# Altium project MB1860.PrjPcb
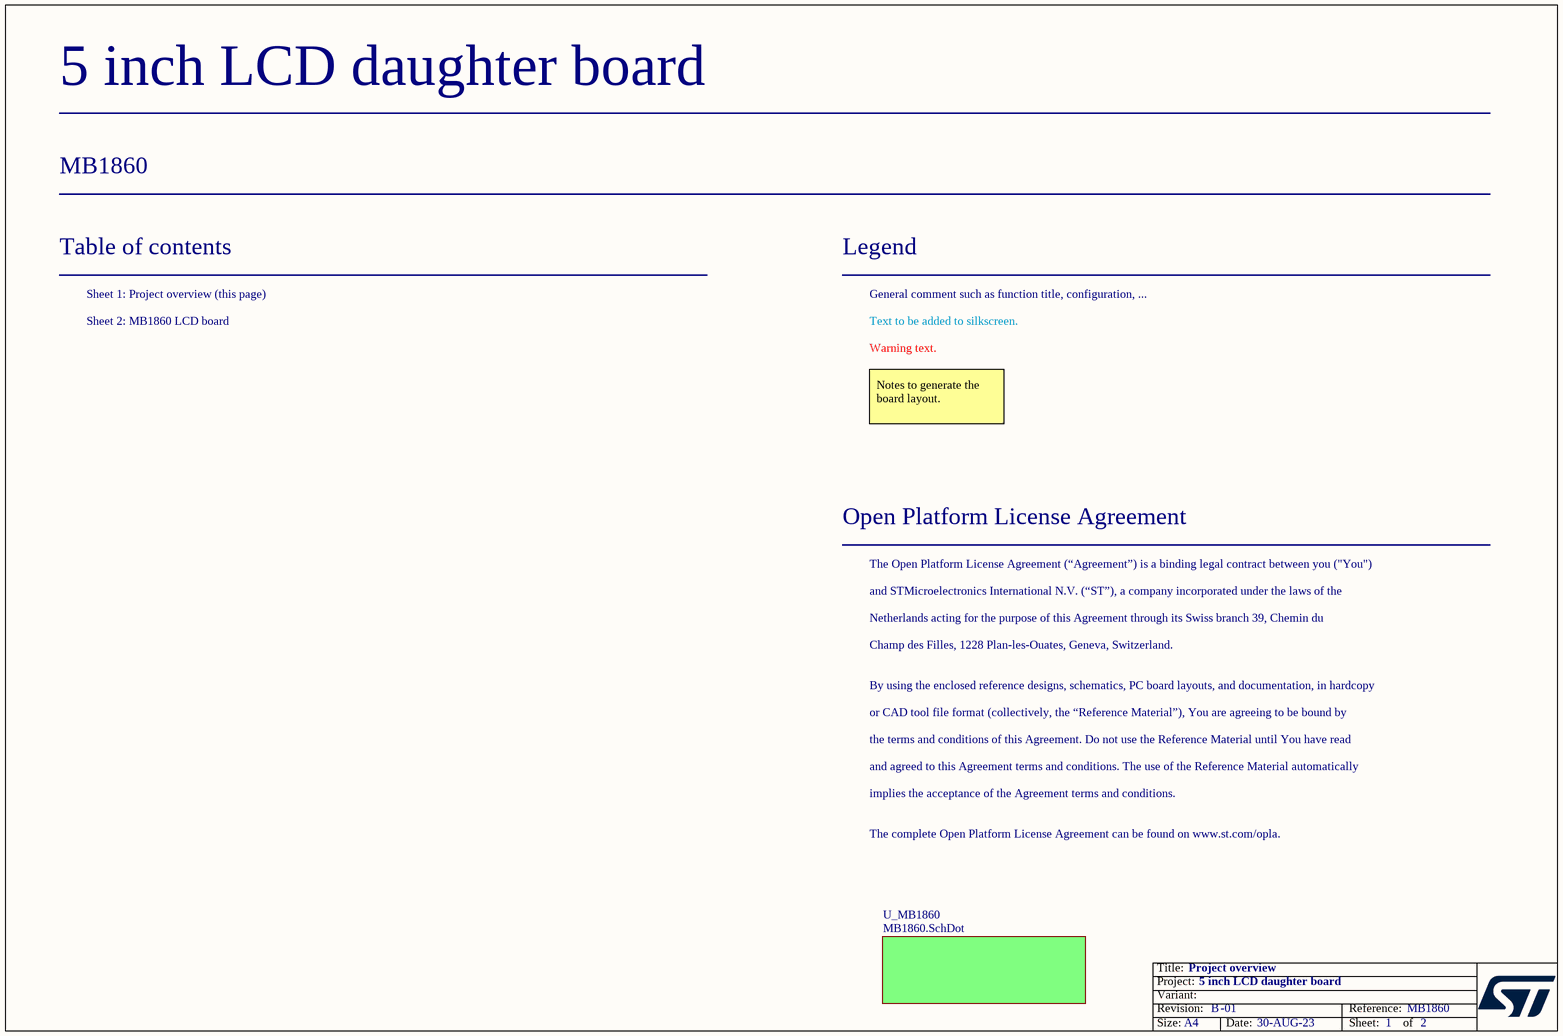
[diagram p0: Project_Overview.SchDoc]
Board_Assembly_Revision: 01; Board_Document_Date: 30-AUG-23; Board_Name: 5 inch LCD daughter board; Board_PCB_Revision: B; Board_Reference: MB1860
2 sheets, 42 parts. Net scope: global (net labels, ports and power ports of the same name join across sheets).
Board file: MB1860.PcbDoc
Sheets:
  Project_Overview.SchDoc
  MB1860.SchDoc

## Sheet Project_Overview.SchDoc: Project overview
size A4; Date: Not used; ApprovedBy: Not used; CheckedBy: Not used; Author: Not used; CompanyName: STMicroelectronics; DrawnBy: Not used; Engineer: Not used; Organization: Not used; Address1: Not used; Address2: Not used; Address3: Not used; Address4: Not used; DocumentNumber: Not used; Revision: Not used; SheetNumber: 1; SheetTotal: 2

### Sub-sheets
U_MB1860 = MB1860.SchDot (file not in this document): no entries

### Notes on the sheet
- Table of contents
- Sheet 1: Project overview (this page)
- Legend
- General comment such as function title, configuration, ...
- Sheet 2: MB1860 LCD board
- Text to be added to silkscreen.
- Warning text.
- Notes to generate the board layout.
- Open Platform License Agreement
- The Open Platform License Agreement (“Agreement”) is a binding legal contract between you ("You")
- and STMicroelectronics International N.V. (“ST”), a company incorporated under the laws of the
- Netherlands acting for the purpose of this Agreement through its Swiss branch 39, Chemin du
- Champ des Filles, 1228 Plan-les-Ouates, Geneva, Switzerland.
- By using the enclosed reference designs, schematics, PC board layouts, and documentation, in hardcopy
- or CAD tool file format (collectively, the “Reference Material”), You are agreeing to be bound by
- the terms and conditions of this Agreement. Do not use the Reference Material until You have read
- and agreed to this Agreement terms and conditions. The use of the Reference Material automatically
- implies the acceptance of the Agreement terms and conditions.
- The complete Open Platform License Agreement can be found on www.st.com/opla.

## Sheet MB1860.SchDoc: MB1860
size A4; Date: Not used; ApprovedBy: Not used; CheckedBy: Not used; Author: Not used; CompanyName: STMicroelectronics; DrawnBy: Not used; Engineer: Not used; Organization: Not used; Address1: Not used; Address2: Not used; Address3: Not used; Address4: Not used; DocumentNumber: Not used; Revision: Not used; SheetNumber: 2; SheetTotal: 2
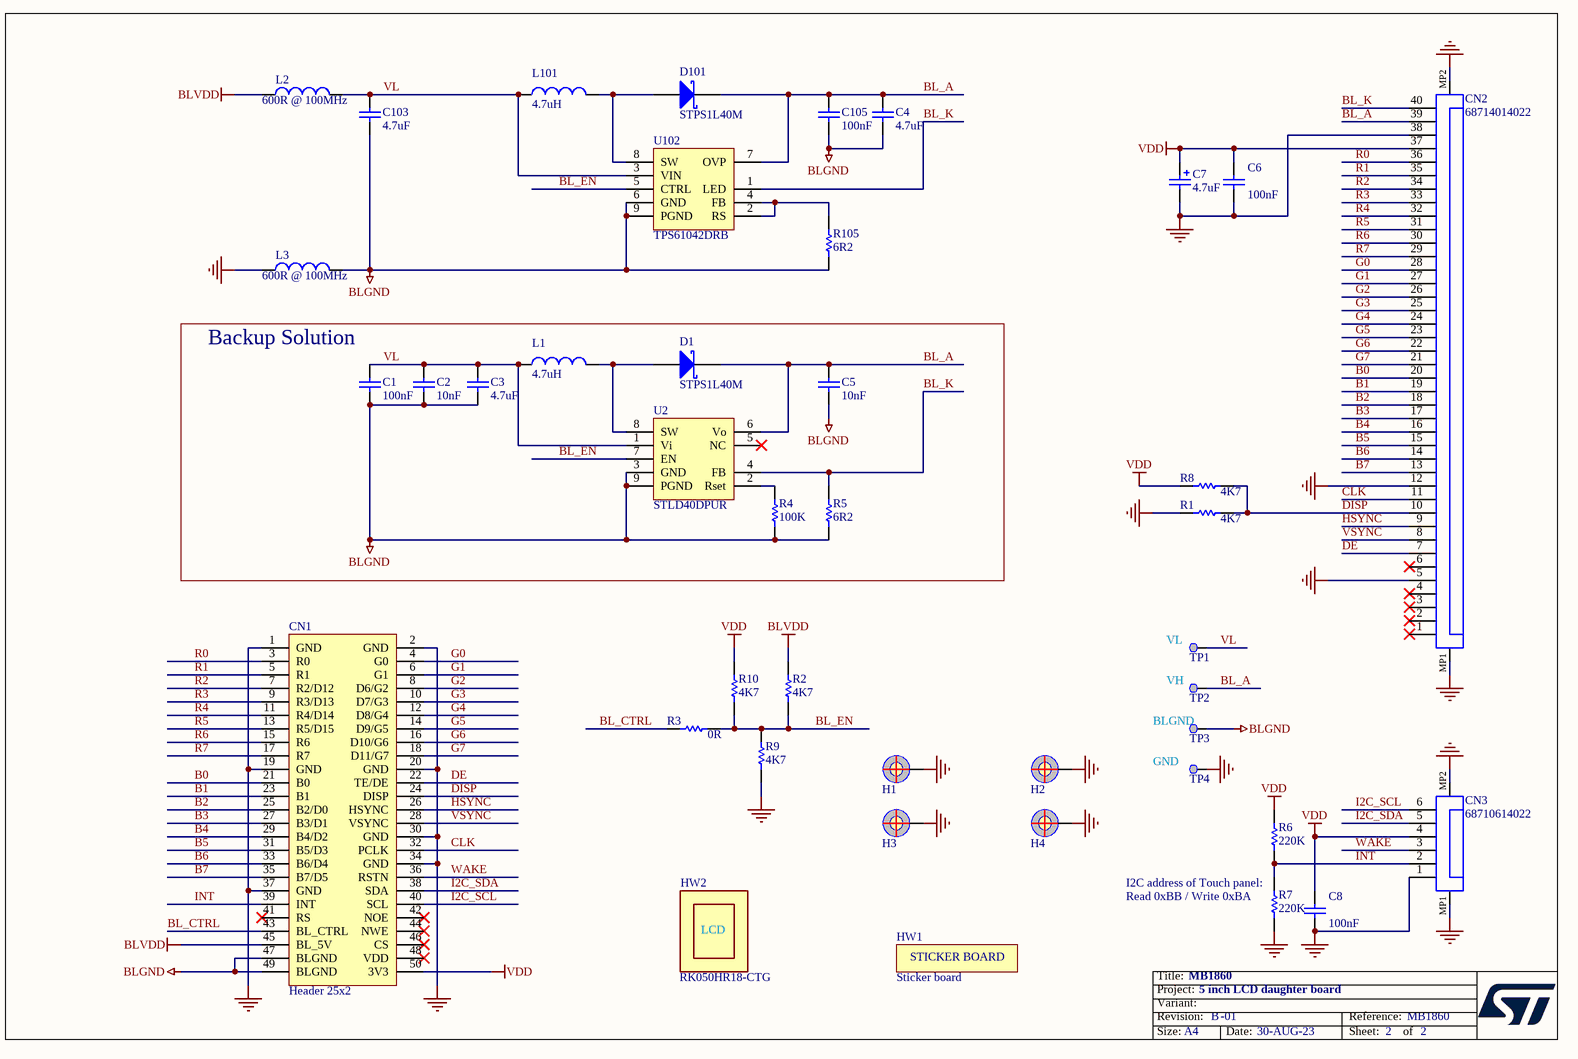
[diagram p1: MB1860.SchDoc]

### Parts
C1  value 100nF  [C0603]  (hidden comment: Capacitor)
C2  value 10nF  [C0603]  (hidden comment: Capacitor)
C3  value 4.7uF  [C1206_H1P25]  (hidden comment: Capacitor)
C4  value 4.7uF  [C1206_H1P25]  (hidden comment: Capacitor)
C5  value 10nF  [C0603]  (hidden comment: Capacitor)
C6  value 100nF  [C0603]  (hidden comment: Capacitor)
C7  value 4.7uF  [CPOL_TAJ-A_1206_H180]  (hidden comment: Cap_POL_TANA)
C8  value 100nF  [C0603]  (hidden comment: Capacitor)
C103  value 4.7uF  [C1206_H1P25]  (hidden comment: Capacitor)
C105  value 100nF  [C0603]  (hidden comment: Capacitor)
CN1  value Header 25x2  [CON_SAMTEC_FTSH-125-01-F-DV-K]  (hidden comment: Header 25x2 LCD MODULE)
CN2  68714014022  [CON_WE_68714014022]
CN3  68710614022  [CON_WE_68710614022]
D1  STPS1L40M  [DIO_DO216-AA]
D101  STPS1L40M  [DIO_DO216-AA]
H1  POSITION HOLE  [PTH_450_900]  (value not drawn)  (no BOM)
H2  POSITION HOLE  [PTH_450_900]  (value not drawn)  (no BOM)
H3  POSITION HOLE  [PTH_450_900]  (value not drawn)  (no BOM)
H4  POSITION HOLE  [PTH_450_900]  (value not drawn)  (no BOM)
HW1  value Sticker board  [STICKER_BOARD_25X9]  (hidden comment: STICKER_BOARD)  (no BOM)
HW2  value RK050HR18-CTG  [LCD_DRAWING_ROCKTEK_RK050HR18-CTG]  (hidden comment: LCD_MODULE)
L1  value 4.7uH  [L1210_LQH]  (hidden comment: Inductor)
L2  value 600R @ 100MHz  [L0603]  (hidden comment: BEAD)
L3  value 600R @ 100MHz  [L0603]  (hidden comment: BEAD)
L101  value 4.7uH  [L1210_LQH]  (hidden comment: Inductor)
R1  value 4K7  [R0603]  (hidden comment: Resistor)
R2  value 4K7  [R0603]  (hidden comment: Resistor)
R3  value 0R  [R0603]  (hidden comment: Resistor)
R4  value 100K  [R0603]  (hidden comment: Resistor)
R5  value 6R2  [R0805_H0P5]  (hidden comment: Resistor)
R6  value 220K  [R0603]  (hidden comment: Resistor)
R7  value 220K  [R0603]  (hidden comment: Resistor)
R8  value 4K7  [R0603]  (hidden comment: Resistor)
R9  value 4K7  [R0603]  (hidden comment: Resistor)
R10  value 4K7  [R0603]  (hidden comment: Resistor)
R105  value 6R2  [R0805_H0P5]  (hidden comment: Resistor)
TP1  Test Point  [TP_SMD_2MM]  (value not drawn)  (no BOM)
TP2  Test Point  [TP_SMD_2MM]  (value not drawn)  (no BOM)
TP3  Test Point  [TP_SMD_2MM]  (value not drawn)  (no BOM)
TP4  Test Point  [TP_SMD_2MM]  (value not drawn)  (no BOM)
U2  STLD40DPUR  [ICC_QFN8-EPAD_3X3_P065]
U102  TPS61042DRB  [ICC_QFN8-EPAD_3X3_P065]

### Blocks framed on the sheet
Backup Solution: C1-C3 C5 D1 L1 R4 R5 U2

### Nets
BLGND: C1.1 C2.1 C3.1 C4.1 C5.1 C103.1 C105.1 CN1.47(BLGND) CN1.49(BLGND) L3.2 R4.1 R5.1 R105.1 TP3.1 U2.3(GND) U2.9(PGND) U102.6(GND) U102.9(PGND)
BLVDD: CN1.45(BL_5V) L2.1 R2.1
GND: C6.1 C7.2 C8.1 CN1.1(GND) CN1.2(GND) CN1.19(GND) CN1.20(GND) CN1.30(GND) CN1.34(GND) CN1.37(GND) CN2.5 CN2.12 CN2.38 CN2.MP1 CN2.MP2 CN3.1 CN3.MP1 CN3.MP2 H1.1 H2.1 H3.1 H4.1 L3.1 R1.1 R7.1 R9.2 TP4.1
VDD: C6.2 C7.1 C8.2 CN1.50(3V3) CN2.37 CN3.4 R6.2 R8.1 R10.1
B0: CN1.21(B0) CN2.20
B1: CN1.23(B1) CN2.19
B2: CN1.25(B2/D0) CN2.18
B3: CN1.27(B3/D1) CN2.17
B4: CN1.29(B4/D2) CN2.16
B5: CN1.31(B5/D3) CN2.15
B6: CN1.33(B6/D4) CN2.14
B7: CN1.35(B7/D5) CN2.13
BL_A: C4.2 C5.2 C105.2 CN2.39 D1.2(K) D101.2(K) TP2.1 U2.6(Vo) U102.7(OVP)
BL_CTRL: CN1.43(BL_CTRL) R3.1
BL_EN: R2.2 R3.2 R9.1 R10.2 U2.7(EN) U102.5(CTRL)
BL_K: CN2.40 R5.2 U2.4(FB) U102.1(LED)
CLK: CN1.32(PCLK) CN2.11
DE: CN1.22(TE/DE) CN2.7
DISP: CN1.24(DISP) CN2.10 R1.2 R8.2
G0: CN1.4(G0) CN2.28
G1: CN1.6(G1) CN2.27
G2: CN1.8(D6/G2) CN2.26
G3: CN1.10(D7/G3) CN2.25
G4: CN1.12(D8/G4) CN2.24
G5: CN1.14(D9/G5) CN2.23
G6: CN1.16(D10/G6) CN2.22
G7: CN1.18(D11/G7) CN2.21
HSYNC: CN1.26(HSYNC) CN2.9
I2C_SCL: CN1.40(SCL) CN3.6
I2C_SDA: CN1.38(SDA) CN3.5
INT: CN1.39(INT) CN3.2 R6.1 R7.2
R0: CN1.3(R0) CN2.36
R1: CN1.5(R1) CN2.35
R2: CN1.7(R2/D12) CN2.34
R3: CN1.9(R3/D13) CN2.33
R4: CN1.11(R4/D14) CN2.32
R5: CN1.13(R5/D15) CN2.31
R6: CN1.15(R6) CN2.30
R7: CN1.17(R7) CN2.29
VL: C1.2 C2.2 C3.2 C103.2 L1.1 L2.2 L101.1 TP1.1 U2.1(Vi) U102.3(VIN)
VSYNC: CN1.28(VSYNC) CN2.8
WAKE: CN1.36(RSTN) CN3.3
NetD1_1: D1.1(A) L1.2 U2.8(SW)
NetD101_1: D101.1(A) L101.2 U102.8(SW)
NetR4_2: R4.2 U2.2(Rset)
NetR105_2: R105.2 U102.2(RS) U102.4(FB)

Not connected (* = marked no-connect by the designer): CN1 41(RS)* 42(NOE)* 44(NWE)* 46(CS)* 48(VDD)*; CN2 1* 2* 3* 4* 6*; U2 5(NC)*

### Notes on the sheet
- (near TP1) VL
- (near TP3) BLGND
- (near TP2) VH
- GND
- (near R7) I2C address of Touch panel:
- (near R7) Read 0xBB / Write 0xBA
- Title:
- Project:
- Size:
- Revision:
- Variant:
- A4
- -
- Date:
- Reference:
- Sheet:
- of

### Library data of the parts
C1 C6 C8 = MCD-00211: Capacitor, MLCC, 100nF, 16V, X7R, +/-10%, 0603, T=0.8mm; Part_Preference: Recommended; Manufacturer: YAGEO; Manufacturer_Part_Number: CC0603KRX7R7BB104; Order_Code_RS: 669-8763; Component_Country_Of_Origin: China; ShowFields: YES; ID: 2659
C2 C5 = MCD-00017: Capacitor, MLCC, 10nF, 50V, X7R, +/-10%, 0603, T=0.8mm; Part_Preference: Recommended; Manufacturer: YAGEO; Manufacturer_Part_Number: CC0603KRX7R9BB103; Order_Code_RS: 616-9537; Component_Country_Of_Origin: China; ShowFields: YES; ID: 2500
C3 C4 C103 = MCD-00013: Capacitor, MLCC, 4.7uF, 50V, X7R, +/-10%, 1206, T=1.27mm; Part_Preference: Recommended; Manufacturer: AVX; Manufacturer_Part_Number: 12065C475KAT2A; Order_Code_RS: 178-0947; Component_Country_Of_Origin: China, Penang; ShowFields: YES; ID: 2466
C7 = MCD-00007: Capacitor, Tantalum, 4.7uF, 16V, 4R, +/-10%, Type_A (3216 metric), T=1.6mm; Part_Preference: Recommended; Manufacturer: AVX; Manufacturer_Part_Number: TAJA475K016R; Order_Code_RS: 464-9132; Component_Country_Of_Origin: El Salvador; ShowFields: YES; ID: 2473
C105 = MCD-01099: Capacitor, MLCC, 100nF, 50V, X7R, +/-10%, 0603, T=0.8mm; BMS_Part_Number: 9142278; Part_Preference: Recommended; Manufacturer: YAGEO; Manufacturer_Part_Number: CC0603KRX7R9BB104; Order_Code_RS: 669-8767; Component_Country_Of_Origin: China; ShowFields: YES; ID: 3397
CN1 = MCD-01187: Header, 25x2, 1.27mm, VR, SMD, T=3.05mm; Part_Type: Connector; Part_Preference: Recommended; Manufacturer: SAMTEC; Manufacturer_Part_Number: FTSH-125-01-F-DV-K; Order_Code_RS: 208-1518; Component_Country_Of_Origin: China, Costa Rica, Malaysia, United States, Vietnam; ShowFields: YES; ID: 3304
CN2 = MCD-02724: Socket_FFC/FPC, 40pins, 0.5mm, RA, SMD, T=2.1mm, TOP Contact; Part_Type: Connector; Part_Preference: Recommended; Manufacturer: WURTH ELEKTRONIK; Value: Socket_FFC/FPC_68714014022; Order_Code_RS: 763-6732; ShowFields: YES; ID: 4821
CN3 = MCD-02725: Socket_FFC/FPC, 6pins, 0.5mm, RA, SMD, T=2.1mm, TOP Contact; Part_Type: Connector; Part_Preference: Recommended; Manufacturer: WURTH ELEKTRONIK; Value: Socket_FFC/FPC_68710614022; Order_Code_RS: 763-2648; ShowFields: YES; ID: 4837
D1 D101 = MCD-00033: Low Drop power Schottky rectifier(1A, 40V, 0.4V); BMS_Part_Number: 9151085; Part_Type: Diode; Part_Preference: Recommended; Manufacturer: STMICROELECTRONICS; Manufacturer_HQ_COO: EU; Component_Country_Of_Origin: China; ShowFields: YES; ID: 2485
H1-H4 = MCD-01612: POSITION HOLE C9D4R5; Part_Type: Misc; Part_Preference: Recommended; ShowFields: YES; ID: 3712
HW1 = MCD-00235: Sticker Board 25x9 mm; Part_Type: Misc; Part_Preference: Recommended; ShowFields: YES; ID: 2632
HW2 = MCD-02602: LCD, 5.0 inch, TFT, 800*480 Pixels with LED backlight, All viewing angle, Capacitive Panel; Part_Type: Display; Part_Preference: Recommended; Manufacturer: ROCKTECH; Component_Country_Of_Origin: China; ShowFields: YES; ID: 4708
L1 L101 = MCD-00048: Inductor, 4.7uH, +/-30%, 1A, 180mR, 1210, T=1.7mm; Part_Preference: Recommended; Manufacturer: MURATA; Manufacturer_Part_Number: LQH32PN4R7NN0L; Order_Code_RS: 167-4086; Component_Country_Of_Origin: Japan; ShowFields: YES; ID: 2544
L2 L3 = MCD-00047: Ferrite bead, 600R @1 00MHz, +/-25%, 350mA, 0R5, 0603, T=0.8mm; Part_Type: Inductor; Part_Preference: Recommended; Manufacturer: TAI-TECH; Manufacturer_Part_Number: FCM1608KF-601T03; Component_Country_Of_Origin: Unknown; ShowFields: YES; ID: 2546
R1 R2 R8-R10 = MCD-00219: Resistor, 4K7, 0603, +/-1%, 1/10W; Part_Preference: Recommended; Manufacturer: YAGEO; Manufacturer_Part_Number: RC0603FR-074K7L; Component_Country_Of_Origin: China; ShowFields: YES; ID: 2648
R3 = MCD-00056: Resistor, 0R, 0603, +/-5%, 1/10W; Part_Preference: Recommended; Manufacturer: YAGEO; Manufacturer_Part_Number: RC0603JR-070RL; Component_Country_Of_Origin: China; ShowFields: YES; ID: 2536
R4 = MCD-00223: Resistor, 100K, 0603, +/- 1%, 1/10W; Part_Preference: Recommended; Manufacturer: YAGEO; Manufacturer_Part_Number: RC0603FR-07100KL; Component_Country_Of_Origin: China; ShowFields: YES; ID: 2647
R5 R105 = MCD-02728: Resistor, 6R2, 0805, +/-1%, 1/8W; Part_Preference: Recommended; Manufacturer: YAGEO; Manufacturer_Part_Number: RC0805FR-076R2L; ShowFields: YES; ID: 4840
R6 R7 = MCD-00347: Resistor, 220K, 0603, +/-1%, 1/10W; Part_Preference: Recommended; Manufacturer: YAGEO; Manufacturer_Part_Number: RC0603FR-07220KL; Component_Country_Of_Origin: China; ShowFields: YES; ID: 2930
TP1-TP4 = MCD-00177: Test Point 2mm; Part_Type: Misc; Part_Preference: Recommended; ShowFields: YES; ID: 2690
U2 = MCD-00082: White LED power supply for large display backlight, QFN8; BMS_Part_Number: 9176009; Part_Type: IC; Part_Preference: Recommended; Manufacturer: STMICROELECTRONICS; Manufacturer_HQ_COO: EU; Component_Country_Of_Origin: Malaysia; ShowFields: YES; ID: 2510
U102 = MCD-02727: 30-V, 500-mA switch boost converter in QFN-8 for white LED applications; Part_Type: IC; Part_Preference: Recommended; Manufacturer: TEXAS INSTRUMENTS; ShowFields: YES; ID: 4839

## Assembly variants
RK050HR18C: not fitted C1 C2 C3 C5 C105 D1 L1 R2 R4 R5 R6 R8 R10 U2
